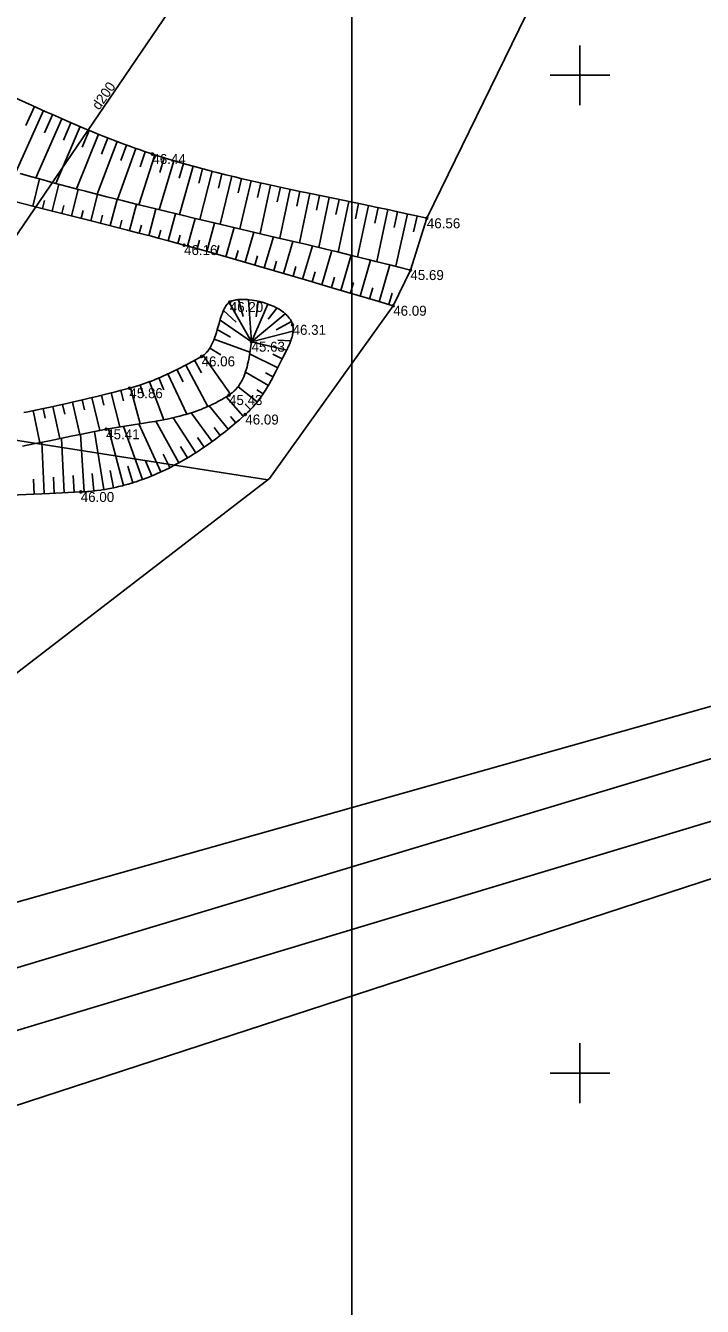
# Model space of a CAD drawing. Extents: x 561134 to 561329, y 413819 to 414116.
# Drawn here: x 561222.2 to 561256.1, y 413888.3 to 413952.5 of the extents above; entities that cross this region are included whole.
import ezdxf

# ---------------------------------------------------------------- set-up
doc = ezdxf.new("R2010")
doc.units = 0
for name, color, linetype in [('BUVE_INZE_VEKT_####_#', 7, 'Continuous'), ('GEOD_ELEM_####_####_#', 7, 'Continuous'), ('RAMI_PLAN_####_TKST_#', 7, 'Continuous'), ('RAMI_UZMR_####_####_#', 7, 'Continuous'), ('RELJ_AATZ_####_TKST_#', 7, 'Continuous'), ('RELJ_ELEM_####_####_#', 7, 'Continuous'), ('RELJ_NOGA_####_####_#', 7, 'Continuous'), ('RELJ_NOGL_####_####_#', 7, 'Continuous'), ('ROBZ_UZMR_####_####_#', 7, 'Continuous'), ('SKAN_VADP_PAST_####_#', 7, 'Continuous'), ('SKAN_VADP_PAST_TKST_#', 7, 'Continuous')]:
    doc.layers.add(name, color=color, linetype=linetype)

msp = doc.modelspace()

# ---------------------------------------------------------------- linework, layer by layer
at = {"layer": 'BUVE_INZE_VEKT_####_#'}
for p, q in [((561207.261, 413900.89), (561273.063, 413920.725)), ((561274.707, 413918.088), (561207.976, 413897.972))]:
    msp.add_line(p, q, dxfattribs=at)
at = {"layer": 'GEOD_ELEM_####_####_#'}
for p, q in [((561250, 413951.5), (561250, 413950)), ((561248.5, 413950), (561250, 413950)), ((561250, 413950), (561250, 413948.5)), ((561250, 413950), (561251.5, 413950)), ((561250, 413901.5), (561250, 413900)), ((561248.5, 413900), (561250, 413900)), ((561250, 413900), (561250, 413898.5)), ((561250, 413900), (561251.5, 413900))]:
    msp.add_line(p, q, dxfattribs=at)
at = {"layer": 'RAMI_PLAN_####_TKST_#'}
msp.add_line((561238.578, 413819.495), (561238.578, 413967.995), dxfattribs=at)
at = {"layer": 'RAMI_UZMR_####_####_#'}
msp.add_lwpolyline([(561254.18, 413993.826), (561250.885, 413973.719), (561248.352, 413955.204), (561242.331, 413942.835), (561241.508, 413940.241), (561240.647, 413938.452), (561234.45, 413929.795), (561214.305, 413914.287), (561206.991, 413896.237), (561188.512, 413892.082)], dxfattribs=at)
at = {"layer": 'RELJ_ELEM_####_####_#'}
for centre in [(561228.584, 413946.055), (561242.331, 413942.835), (561230.172, 413941.492), (561241.508, 413940.241), (561232.462, 413938.64), (561240.647, 413938.452), (561235.607, 413937.495), (561233.551, 413936.649), (561231.049, 413935.914), (561227.434, 413934.321), (561232.424, 413933.976), (561233.24, 413933.001), (561226.271, 413932.263), (561224.998, 413929.12)]:
    msp.add_circle(centre, 0.05, dxfattribs=at)
at = {"layer": 'RELJ_NOGA_####_####_#'}
for p, q in [((561223.13, 413948.229), (561221.744, 413945.145)), ((561222.674, 413948.434), (561222.249, 413947.49)), ((561224.044, 413947.824), (561222.75, 413944.859)), ((561223.586, 413948.025), (561223.186, 413947.118)), ((561224.963, 413947.428), (561223.753, 413944.584)), ((561224.503, 413947.625), (561224.126, 413946.754)), ((561225.424, 413947.235), (561225.076, 413946.398)), ((561225.886, 413947.046), (561224.784, 413944.307)), ((561226.817, 413946.68), (561225.812, 413944.039)), ((561226.351, 413946.861), (561226.033, 413946.055)), ((561227.756, 413946.336), (561226.84, 413943.778)), ((561227.286, 413946.505), (561226.999, 413945.725)), ((561228.704, 413946.017), (561227.902, 413943.513)), ((561228.229, 413946.173), (561227.975, 413945.413)), ((561229.659, 413945.721), (561228.93, 413943.261)), ((561229.18, 413945.866), (561228.951, 413945.122)), ((561230.139, 413945.582), (561229.928, 413944.849)), ((561230.62, 413945.446), (561229.943, 413943.017)), ((561231.103, 413945.315), (561230.909, 413944.589)), ((561222.597, 413943.446), (561222.939, 413944.807)), ((561231.587, 413945.189), (561230.957, 413942.775)), ((561232.071, 413945.066), (561231.891, 413944.343)), ((561232.557, 413944.947), (561231.972, 413942.536)), ((561233.043, 413944.831), (561232.875, 413944.106)), ((561233.53, 413944.718), (561232.971, 413942.301)), ((561234.018, 413944.608), (561233.854, 413943.88)), ((561223.567, 413943.202), (561223.905, 413944.543)), ((561224.537, 413942.958), (561224.871, 413944.284)), ((561225.506, 413942.713), (561225.842, 413944.032)), ((561234.506, 413944.5), (561233.976, 413942.065)), ((561234.995, 413944.393), (561234.838, 413943.66)), ((561235.484, 413944.289), (561234.965, 413941.833)), ((561235.973, 413944.186), (561235.819, 413943.445)), ((561236.463, 413944.084), (561235.946, 413941.601)), ((561236.952, 413943.983), (561236.798, 413943.234)), ((561223.082, 413943.324), (561223.184, 413943.729)), ((561224.052, 413943.08), (561224.153, 413943.479)), ((561226.475, 413942.466), (561226.814, 413943.784)), ((561227.444, 413942.217), (561227.788, 413943.541)), ((561237.442, 413943.882), (561236.925, 413941.369)), ((561237.932, 413943.782), (561237.776, 413943.023)), ((561238.422, 413943.681), (561237.898, 413941.137)), ((561238.911, 413943.58), (561238.753, 413942.812)), ((561239.401, 413943.478), (561238.862, 413940.903)), ((561239.89, 413943.375), (561239.725, 413942.598)), ((561225.022, 413942.836), (561225.121, 413943.232)), ((561225.991, 413942.59), (561226.091, 413942.985)), ((561226.96, 413942.342), (561227.062, 413942.738)), ((561228.411, 413941.964), (561228.763, 413943.302)), ((561229.378, 413941.707), (561229.741, 413943.065)), ((561230.343, 413941.445), (561230.723, 413942.831)), ((561240.379, 413943.271), (561239.824, 413940.666)), ((561240.868, 413943.165), (561240.694, 413942.381)), ((561241.356, 413943.057), (561240.775, 413940.428)), ((561241.844, 413942.948), (561241.661, 413942.157)), ((561242.331, 413942.835), (561242.331, 413942.834)), ((561227.928, 413942.091), (561228.032, 413942.49)), ((561228.895, 413941.836), (561229.003, 413942.24)), ((561231.307, 413941.178), (561231.702, 413942.599)), ((561232.269, 413940.906), (561232.686, 413942.368)), ((561233.23, 413940.63), (561233.665, 413942.138)), ((561229.86, 413941.576), (561229.972, 413941.988)), ((561230.825, 413941.312), (561230.942, 413941.733)), ((561231.788, 413941.042), (561231.91, 413941.475)), ((561234.19, 413940.352), (561234.646, 413941.908)), ((561235.15, 413940.07), (561235.621, 413941.678)), ((561236.109, 413939.788), (561236.599, 413941.447)), ((561232.75, 413940.769), (561232.878, 413941.214)), ((561233.71, 413940.491), (561233.844, 413940.951)), ((561237.068, 413939.504), (561237.574, 413941.214)), ((561238.027, 413939.221), (561238.547, 413940.979)), ((561238.987, 413938.938), (561239.517, 413940.742)), ((561234.67, 413940.211), (561234.809, 413940.686)), ((561235.63, 413939.929), (561235.774, 413940.419)), ((561236.589, 413939.646), (561236.738, 413940.151)), ((561239.946, 413938.656), (561240.484, 413940.501)), ((561237.548, 413939.362), (561237.702, 413939.883)), ((561238.507, 413939.079), (561238.664, 413939.614)), ((561239.466, 413938.797), (561239.627, 413939.344)), ((561240.426, 413938.516), (561240.589, 413939.075)), ((561232.142, 413938.21), (561232.774, 413937.634)), ((561232.425, 413938.615), (561233.551, 413936.649)), ((561232.897, 413938.761), (561233.136, 413937.915)), ((561233.397, 413938.757), (561233.551, 413936.649)), ((561234.369, 413938.536), (561233.551, 413936.649)), ((561233.89, 413938.677), (561233.777, 413937.9)), ((561234.826, 413938.333), (561234.392, 413937.788)), ((561233.551, 413936.649), (561231.978, 413937.738)), ((561235.238, 413938.052), (561233.551, 413936.649)), ((561235.546, 413937.663), (561234.789, 413937.252)), ((561231.837, 413937.258), (561232.501, 413936.878)), ((561233.551, 413936.649), (561235.627, 413937.176)), ((561231.464, 413936.334), (561232.008, 413936.001)), ((561231.68, 413936.784), (561233.468, 413936.125)), ((561235.312, 413936.234), (561233.551, 413936.649)), ((561234.861, 413936.728), (561235.515, 413936.691)), ((561230.696, 413935.719), (561231.038, 413935.093)), ((561231.131, 413935.966), (561232.5, 413934.028)), ((561234.862, 413935.341), (561233.455, 413936.042)), ((561235.085, 413935.789), (561234.62, 413936.02)), ((561229.361, 413935.036), (561230.305, 413933.018)), ((561229.811, 413935.253), (561230.124, 413934.637)), ((561230.256, 413935.482), (561231.354, 413933.4)), ((561234.394, 413934.458), (561233.248, 413935.13)), ((561234.635, 413934.896), (561234.254, 413935.095)), ((561227.49, 413934.336), (561227.978, 413932.539)), ((561227.969, 413934.479), (561228.155, 413933.926)), ((561228.441, 413934.645), (561229.152, 413932.739)), ((561228.904, 413934.832), (561229.154, 413934.242)), ((561233.833, 413933.631), (561232.875, 413934.396)), ((561225.065, 413933.731), (561225.178, 413933.242)), ((561225.551, 413933.847), (561225.949, 413932.201)), ((561226.037, 413933.965), (561226.161, 413933.464)), ((561226.522, 413934.086), (561226.953, 413932.38)), ((561227.006, 413934.21), (561227.143, 413933.685)), ((561233.14, 413932.912), (561232.279, 413933.885)), ((561234.129, 413934.034), (561233.816, 413934.245)), ((561222.622, 413933.197), (561222.945, 413931.589)), ((561223.112, 413933.297), (561223.212, 413932.815)), ((561223.601, 413933.401), (561223.948, 413931.796)), ((561224.09, 413933.508), (561224.197, 413933.025)), ((561224.578, 413933.618), (561224.952, 413932.003)), ((561231.586, 413931.655), (561230.534, 413933.089)), ((561232.378, 413932.264), (561231.422, 413933.43)), ((561233.503, 413933.255), (561233.235, 413933.513)), ((561228.086, 413929.746), (561227.136, 413932.409)), ((561229.011, 413930.125), (561227.908, 413932.528)), ((561229.903, 413930.576), (561228.761, 413932.666)), ((561230.761, 413931.089), (561229.633, 413932.841)), ((561232.763, 413932.584), (561232.494, 413932.903)), ((561224.162, 413929.083), (561224.04, 413931.814)), ((561225.161, 413929.129), (561224.988, 413932.01)), ((561226.154, 413929.24), (561225.685, 413932.15)), ((561227.132, 413929.447), (561226.387, 413932.284)), ((561231.178, 413931.366), (561230.852, 413931.843)), ((561231.986, 413931.954), (561231.687, 413932.343)), ((561223.163, 413929.038), (561223.05, 413931.611)), ((561230.336, 413930.825), (561229.991, 413931.401)), ((561228.552, 413929.925), (561228.246, 413930.689)), ((561229.461, 413930.342), (561229.118, 413931.017)), ((561223.662, 413929.06), (561223.627, 413929.856)), ((561224.661, 413929.105), (561224.623, 413929.949)), ((561225.659, 413929.172), (561225.564, 413930.045)), ((561226.645, 413929.332), (561226.469, 413930.199)), ((561227.612, 413929.586), (561227.353, 413930.414)), ((561222.663, 413929.016), (561222.63, 413929.765))]:
    msp.add_line(p, q, dxfattribs=at)
for points in [[(561242.331, 413942.835), (561241.821, 413942.953), (561241.481, 413943.03), (561240.8, 413943.18), (561240.458, 413943.254), (561239.775, 413943.4), (561239.091, 413943.543), (561237.722, 413943.825), (561236.504, 413944.075), (561235.896, 413944.202), (561235.288, 413944.33), (561234.985, 413944.395), (561234.378, 413944.527), (561234.075, 413944.595), (561233.622, 413944.697), (561233.018, 413944.837), (561232.716, 413944.908), (561232.265, 413945.018), (561231.815, 413945.131), (561231.59, 413945.188), (561231.191, 413945.292), (561230.991, 413945.345), (561230.693, 413945.426), (561230.246, 413945.551), (561229.801, 413945.679), (561229.579, 413945.745), (561229.283, 413945.834), (561229.136, 413945.88), (561228.915, 413945.949), (561228.584, 413946.055), (561228.453, 413946.098), (561228.192, 413946.185), (561227.932, 413946.274), (561227.758, 413946.335), (561227.413, 413946.459), (561227.154, 413946.554), (561226.982, 413946.618), (561226.638, 413946.749), (561226.467, 413946.815), (561226.125, 413946.95), (561225.783, 413947.087), (561225.556, 413947.18), (561225.103, 413947.369), (561224.594, 413947.585), (561224.256, 413947.731), (561224.031, 413947.83), (561223.58, 413948.028), (561223.243, 413948.178), (561222.57, 413948.481), (561221.224, 413949.091)], [(561219.689, 413944.182), (561220.854, 413943.885), (561221.632, 413943.688), (561223.187, 413943.297), (561225.26, 413942.776), (561226.296, 413942.512), (561227.331, 413942.246), (561227.848, 413942.112), (561228.538, 413941.931), (561228.882, 413941.84), (561229.398, 413941.702), (561230.172, 413941.492), (561230.562, 413941.385), (561231.34, 413941.169), (561232.117, 413940.949), (561232.635, 413940.802), (561233.67, 413940.503), (561234.188, 413940.353), (561235.221, 413940.05), (561236.255, 413939.745), (561237.632, 413939.337), (561238.321, 413939.134), (561239.871, 413938.678), (561240.647, 413938.452)], [(561220.311, 413928.913), (561223.436, 413929.05), (561224.998, 413929.12), (561225.11, 413929.126), (561225.185, 413929.13), (561225.334, 413929.141), (561225.408, 413929.147), (561225.556, 413929.161), (561225.704, 413929.177), (561225.802, 413929.189), (561225.998, 413929.215), (561226.071, 413929.226), (561226.217, 413929.25), (561226.362, 413929.276), (561226.459, 413929.294), (561226.652, 413929.333), (561226.796, 413929.365), (561226.892, 413929.387), (561227.082, 413929.434), (561227.178, 413929.459), (561227.367, 413929.512), (561227.556, 413929.568), (561227.681, 413929.607), (561227.765, 413929.634), (561227.931, 413929.69), (561228.14, 413929.765), (561228.279, 413929.817), (561228.372, 413929.853), (561228.556, 413929.927), (561228.694, 413929.984), (561228.785, 413930.024), (561228.968, 413930.105), (561229.059, 413930.147), (561229.24, 413930.232), (561229.42, 413930.321), (561229.54, 413930.382), (561229.62, 413930.424), (561229.779, 413930.508), (561229.913, 413930.581), (561230.001, 413930.631), (561230.179, 413930.732), (561230.267, 413930.784), (561230.443, 413930.889), (561230.618, 413930.998), (561230.734, 413931.071), (561230.812, 413931.121), (561230.966, 413931.222), (561231.053, 413931.28), (561231.225, 413931.398), (561231.397, 413931.518), (561231.511, 413931.6), (561231.739, 413931.767), (561231.908, 413931.895), (561232.021, 413931.981), (561232.246, 413932.157), (561232.357, 413932.247), (561232.58, 413932.43), (561232.801, 413932.616), (561232.948, 413932.743), (561233.24, 413933.001), (561233.278, 413933.036), (561233.352, 413933.105), (561233.425, 413933.175), (561233.472, 413933.223), (561233.563, 413933.318), (561233.629, 413933.39), (561233.673, 413933.439), (561233.757, 413933.537), (561233.797, 413933.586), (561233.877, 413933.686), (561233.953, 413933.786), (561234.003, 413933.854), (561234.099, 413933.99), (561234.151, 413934.067), (561234.186, 413934.119), (561234.252, 413934.223), (561234.349, 413934.381), (561234.411, 413934.487), (561234.452, 413934.558), (561234.531, 413934.701), (561234.618, 413934.863), (561234.675, 413934.972), (561234.787, 413935.191), (561235.118, 413935.855), (561235.231, 413936.077), (561235.289, 413936.189), (561235.344, 413936.296), (561235.371, 413936.352), (561235.411, 413936.436), (561235.449, 413936.522), (561235.467, 413936.565), (561235.502, 413936.653), (561235.518, 413936.697), (561235.541, 413936.764), (561235.568, 413936.853), (561235.58, 413936.897), (561235.596, 413936.964), (561235.609, 413937.031), (561235.609, 413937.031), (561235.615, 413937.064), (561235.623, 413937.123), (561235.626, 413937.152), (561235.63, 413937.195), (561235.632, 413937.26), (561235.631, 413937.324), (561235.629, 413937.356), (561235.622, 413937.418), (561235.617, 413937.449), (561235.607, 413937.495), (561235.597, 413937.532), (561235.589, 413937.557), (561235.572, 413937.606), (561235.562, 413937.63), (561235.54, 413937.678), (561235.515, 413937.724), (561235.496, 413937.755), (561235.484, 413937.775), (561235.456, 413937.815), (561235.44, 413937.837), (561235.406, 413937.881), (561235.369, 413937.924), (561235.343, 413937.951), (561235.288, 413938.006), (561235.245, 413938.046), (561235.215, 413938.072), (561235.152, 413938.123), (561235.119, 413938.148), (561235.051, 413938.197), (561234.98, 413938.243), (561234.931, 413938.273), (561234.898, 413938.293), (561234.83, 413938.331), (561234.741, 413938.377), (561234.681, 413938.407), (561234.64, 413938.426), (561234.556, 413938.463), (561234.493, 413938.489), (561234.45, 413938.506), (561234.364, 413938.538), (561234.32, 413938.554), (561234.232, 413938.583), (561234.144, 413938.611), (561234.084, 413938.628), (561233.965, 413938.659), (561233.876, 413938.68), (561233.817, 413938.693), (561233.698, 413938.716), (561233.581, 413938.735), (561233.427, 413938.755), (561233.352, 413938.761), (561233.241, 413938.769), (561233.187, 413938.77), (561233.082, 413938.771), (561233.03, 413938.77), (561232.956, 413938.766), (561232.884, 413938.76), (561232.849, 413938.756), (561232.788, 413938.747), (561232.759, 413938.742), (561232.717, 413938.734), (561232.656, 413938.719), (561232.598, 413938.701), (561232.571, 413938.692), (561232.52, 413938.67), (561232.496, 413938.659), (561232.462, 413938.64), (561232.44, 413938.626), (561232.425, 413938.616), (561232.397, 413938.594), (561232.383, 413938.582), (561232.357, 413938.556), (561232.331, 413938.529), (561232.314, 413938.509), (561232.282, 413938.468), (561232.248, 413938.416), (561232.226, 413938.38), (561232.212, 413938.355), (561232.184, 413938.302), (561232.164, 413938.261), (561232.126, 413938.173), (561232.089, 413938.081), (561232.066, 413938.016), (561232.021, 413937.882), (561231.988, 413937.776), (561231.924, 413937.558), (561231.837, 413937.257), (561231.791, 413937.105), (561231.742, 413936.955), (561231.716, 413936.881), (561231.68, 413936.784), (561231.662, 413936.736), (561231.633, 413936.665), (561231.587, 413936.562), (561231.554, 413936.495), (561231.537, 413936.462), (561231.511, 413936.414), (561231.479, 413936.358), (561231.463, 413936.331), (561231.437, 413936.292), (561231.397, 413936.234), (561231.355, 413936.18), (561231.334, 413936.153), (561231.289, 413936.103), (561231.265, 413936.079), (561231.229, 413936.044), (561231.179, 413936.001), (561231.153, 413935.981), (561231.112, 413935.953), (561231.07, 413935.926), (561231.049, 413935.914), (561230.75, 413935.748), (561230.599, 413935.666), (561230.372, 413935.544), (561230.143, 413935.423), (561230.028, 413935.363), (561229.795, 413935.245), (561229.679, 413935.188), (561229.503, 413935.102), (561229.266, 413934.992), (561229.147, 413934.938), (561228.967, 413934.859), (561228.786, 413934.782), (561228.695, 413934.745), (561228.533, 413934.681), (561228.451, 413934.649), (561228.328, 413934.603), (561228.142, 413934.537), (561227.956, 413934.474), (561227.862, 413934.444), (561227.672, 413934.387), (561227.577, 413934.36), (561227.434, 413934.321), (561226.97, 413934.2), (561226.738, 413934.141), (561226.39, 413934.053), (561225.867, 413933.923), (561225.345, 413933.797), (561225.084, 413933.735), (561224.562, 413933.614), (561224.3, 413933.555), (561223.909, 413933.468), (561223.386, 413933.355), (561223.125, 413933.3), (561222.733, 413933.219), (561222.341, 413933.14), (561222.145, 413933.102)]]:
    msp.add_lwpolyline(points, dxfattribs=at)
at = {"layer": 'RELJ_NOGL_####_####_#'}
for points in [[(561221.97, 413945.08), (561222.477, 413944.936), (561222.858, 413944.829), (561223.112, 413944.759), (561223.62, 413944.619), (561224.384, 413944.413), (561224.893, 413944.278), (561225.234, 413944.189), (561225.914, 413944.013), (561226.298, 413943.915), (561227.065, 413943.721), (561227.834, 413943.529), (561228.347, 413943.403), (561229.373, 413943.154), (561230.143, 413942.969), (561230.657, 413942.846), (561231.686, 413942.603), (561234.772, 413941.878), (561236.315, 413941.514), (561237.343, 413941.27), (561237.857, 413941.146), (561238.627, 413940.96), (561239.396, 413940.772), (561239.781, 413940.677), (561240.549, 413940.485), (561240.933, 413940.388), (561241.508, 413940.241)], [(561222.085, 413931.419), (561222.625, 413931.525), (561222.895, 413931.579), (561223.435, 413931.689), (561224.514, 413931.913), (561225.054, 413932.024), (561225.595, 413932.132), (561225.865, 413932.185), (561226.271, 413932.263), (561226.375, 413932.282), (561226.582, 413932.319), (561226.789, 413932.354), (561227.202, 413932.42), (561227.615, 413932.483), (561228.164, 413932.567), (561228.438, 413932.611), (561228.711, 413932.657), (561228.847, 413932.681), (561229.052, 413932.719), (561229.233, 413932.755), (561229.323, 413932.773), (561229.459, 413932.802), (561229.662, 413932.848), (561229.865, 413932.897), (561229.966, 413932.923), (561230.168, 413932.978), (561230.268, 413933.007), (561230.419, 413933.052), (561230.598, 413933.109), (561230.687, 413933.139), (561230.82, 413933.186), (561230.954, 413933.235), (561231.02, 413933.261), (561231.153, 413933.314), (561231.219, 413933.341), (561231.318, 413933.384), (561231.451, 413933.443), (561231.517, 413933.473), (561231.615, 413933.52), (561231.763, 413933.594), (561231.894, 413933.663), (561231.96, 413933.698), (561232.058, 413933.753), (561232.205, 413933.839), (561232.351, 413933.929), (561232.424, 413933.976), (561232.451, 413933.994), (561232.503, 413934.03), (561232.553, 413934.068), (561232.585, 413934.093), (561232.647, 413934.147), (561232.691, 413934.189), (561232.72, 413934.217), (561232.775, 413934.275), (561232.802, 413934.305), (561232.853, 413934.366), (561232.901, 413934.43), (561232.931, 413934.473), (561232.951, 413934.502), (561232.989, 413934.561), (561233.02, 413934.612), (561233.039, 413934.646), (561233.077, 413934.716), (561233.077, 413934.716), (561233.094, 413934.751), (561233.128, 413934.823), (561233.16, 413934.896), (561233.181, 413934.945), (561233.219, 413935.044), (561233.257, 413935.158), (561233.281, 413935.234), (561233.296, 413935.286), (561233.324, 413935.389), (561233.344, 413935.467), (561233.356, 413935.519), (561233.379, 413935.623), (561233.41, 413935.78), (561233.429, 413935.884), (561233.463, 413936.09), (561233.551, 413936.649)]]:
    msp.add_lwpolyline(points, dxfattribs=at)
at = {"layer": 'ROBZ_UZMR_####_####_#'}
for p, q in [((561270.72, 413922.391), (561195.123, 413901.021)), ((561220.114, 413897.841), (561277.05, 413916.422))]:
    msp.add_line(p, q, dxfattribs=at)
at = {"layer": 'SKAN_VADP_PAST_####_#'}
msp.add_line((561234.729, 413961.018), (561215.454, 413932.7), dxfattribs=at)
msp.add_lwpolyline([(561215.454, 413932.7), (561234.374, 413929.736)], dxfattribs=at)

# ---------------------------------------------------------------- texts
at = {"layer": 'RELJ_AATZ_####_TKST_#'}
for s, p in [('46.44', (561228.584, 413945.555)), ('46.56', (561242.331, 413942.335)), ('46.16', (561230.172, 413940.992)), ('45.69', (561241.508, 413939.741)), ('46.20', (561232.462, 413938.14)), ('46.09', (561240.647, 413937.952)), ('46.31', (561235.607, 413936.995)), ('45.63', (561233.551, 413936.149)), ('46.06', (561231.049, 413935.414)), ('45.86', (561227.434, 413933.821)), ('45.43', (561232.424, 413933.476)), ('46.09', (561233.24, 413932.501)), ('45.41', (561226.271, 413931.763)), ('46.00', (561224.998, 413928.62))]:
    msp.add_text(s, height=0.5, dxfattribs=at).set_placement(p)
at = {"layer": 'SKAN_VADP_PAST_TKST_#'}
msp.add_text('d200', height=0.5, rotation=54.84209, dxfattribs=at).set_placement((561225.916, 413948.225))

doc.saveas('drawing.dxf')
